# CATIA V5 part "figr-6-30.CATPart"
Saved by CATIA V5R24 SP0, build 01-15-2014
Part number: Part1
Bounding box of the stored display mesh (mm): x -61 to 61, y 0 to 173.636, z 0 to 130.49
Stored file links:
  D:\KAVITA\CATIA V5-6R2014 Project_ Kavita\CATIA V5-6R2014_partfiles\Partfiles\c06_catia_v5-6r2014_prt\figr-6-30.CATPart
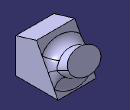
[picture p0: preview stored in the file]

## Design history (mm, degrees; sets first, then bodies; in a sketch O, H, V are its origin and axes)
Body1 (main body)
  Sketch1 on yz-plane, origin (0, 0, 0), H (0, 1, 0), V (0, 0, 1)
    line L1 (0, 0) -> (0, 110.5903)
    line L2 (0, 110.5903) -> (66.2814, 130.4899)
    line L3 (66.2814, 130.4899) -> (135.1646, 0)
    point P3 (135.1646, 0)
    line L4 (135.1646, 0) -> (0, 0)
    vertical: L1 V
    coincidence: P3 H
    horizontal: L4 H
  Pad1: profile Sketch1, direction (1, 0, 0), length 61, mirrored extent
  Sketch2 on face of Pad1, origin (0, 105.7081, 55.8014), H (-1, 0, 0), V (0, -0.4668, 0.8843)
    point P1 (0, 4.9672)
    ellipse A1 centre (0, 4.9672) semi-axes 50.9663, 34.9201 rotation 0
    coincidence: P1 V
  Pad2: profile Sketch2, direction (0, 0.8843, 0.4668), length 61
  Fillet1: radius 29, on edge [face of Pad1 | face of Pad2]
